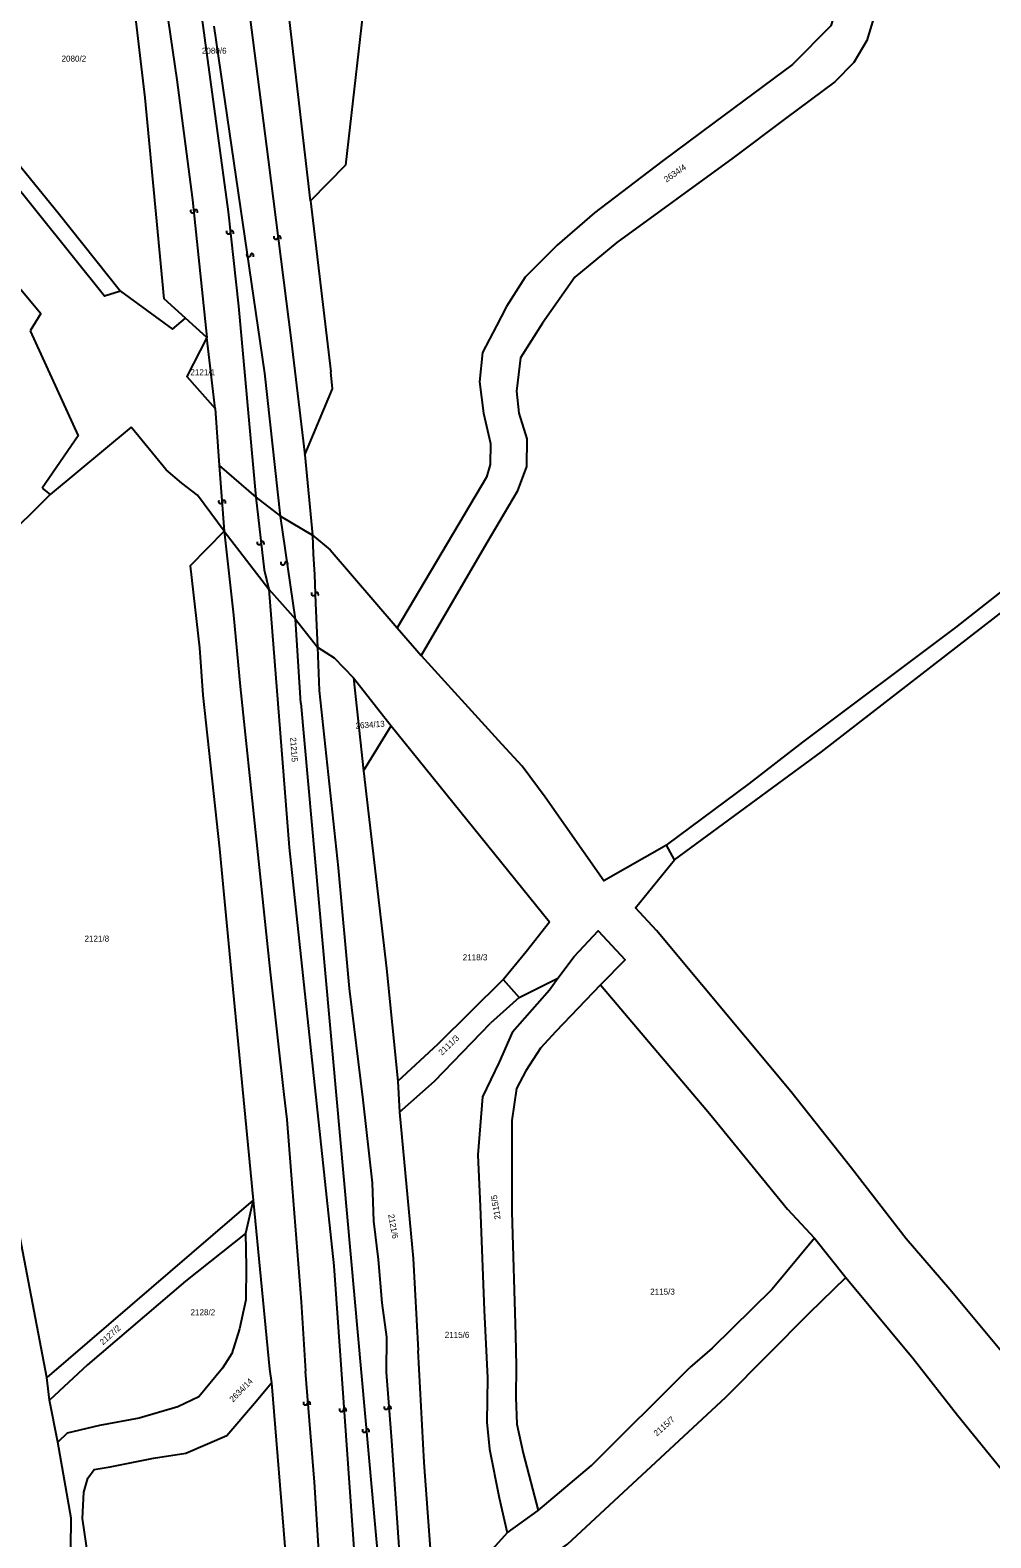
# Model space of a CAD drawing. Extents: x -581999 to -572728, y -1219553 to -1212032.
# Drawn here: x -576394 to -576076, y -1216348 to -1215848 of the extents above; entities that cross this region are included whole.
import ezdxf

# ---------------------------------------------------------------- set-up
doc = ezdxf.new("R2010")
doc.units = 0
for name, color, linetype in [('Vrstva 1', 7, 'Continuous'), ('Vrstva 2', 7, 'Continuous'), ('Vrstva 4', 7, 'Continuous'), ('Vrstva 6', 7, 'Continuous')]:
    doc.layers.add(name, color=color, linetype=linetype)

msp = doc.modelspace()

# ---------------------------------------------------------------- linework, layer by layer
at = {"layer": 'Vrstva 1'}
for p, q in [((-576356.273, -1215870.335), (-576360.8, -1215831.766)), ((-576450.435, -1215870.759), (-576390.81, -1215941.951)), ((-576349.894, -1215937.081), (-576356.273, -1215870.335)), ((-576342.862, -1215943.515), (-576349.894, -1215937.081)), ((-576390.81, -1215941.951), (-576394.345, -1215947.753)), ((-576394.345, -1215947.753), (-576378.44, -1215982.562)), ((-576335.832, -1215949.947), (-576342.862, -1215943.515)), ((-576333.009, -1215973.521), (-576331.724, -1215992.401)), ((-576378.44, -1215982.562), (-576390.368, -1215999.967)), ((-576331.724, -1215992.401), (-576319.52, -1216002.887)), ((-576390.368, -1215999.967), (-576387.717, -1216002.039)), ((-576319.52, -1216002.887), (-576311.344, -1216009.21)), ((-576311.344, -1216009.21), (-576300.762, -1216015.51)), ((-576232.162, -1216169.034), (-576219.332, -1216162.616)), ((-576234.385, -1216180.427), (-576222.069, -1216166.467)), ((-576236.168, -1216346.782), (-576225.819, -1216339.308))]:
    msp.add_line(p, q, dxfattribs=at)
for points in [[(-576104.129, -1215760.392), (-576107.967, -1215765.027), (-576112.258, -1215772.037), (-576115.046, -1215779.052), (-576115.435, -1215786.377), (-576115.542, -1215795.229), (-576116.26, -1215804.993), (-576118.784, -1215815.057), (-576128.771, -1215846.461), (-576141.538, -1215859.243), (-576167.599, -1215878.707), (-576184.873, -1215891.479)], [(-576099.875, -1215781.163), (-576102.579, -1215791.296), (-576102.749, -1215805.334), (-576107.105, -1215817.834), (-576113.38, -1215840.092), (-576116.819, -1215851.371), (-576121.111, -1215858.681), (-576127.493, -1215865.072), (-576143.855, -1215877.236), (-576161.128, -1215890.312), (-576199.747, -1215918.364), (-576213.7, -1215929.925), (-576224.392, -1215945.15), (-576231.735, -1215956.722), (-576233.062, -1215967.695), (-576232.245, -1215975.013), (-576229.639, -1215983.553), (-576229.744, -1215992.696)], [(-576301.376, -1215904.608), (-576308.701, -1215841.562)], [(-576284.007, -1215842.251), (-576289.823, -1215892.731), (-576301.376, -1215904.608)], [(-576407.912, -1215880.699), (-576385.122, -1215908.586), (-576364.389, -1215934.537)], [(-576184.873, -1215891.479), (-576207.144, -1215908.589), (-576219.586, -1215919.238), (-576230.225, -1215929.891), (-576236.347, -1215939.638), (-576239.725, -1215946.035), (-576244.334, -1215954.869), (-576245.346, -1215964.623), (-576243.962, -1215974.992), (-576241.673, -1215985.056), (-576241.753, -1215992.066), (-576243.004, -1215996.331), (-576272.67, -1216046.337)], [(-576301.376, -1215904.608), (-576294.599, -1215961.296)], [(-576131.913, -1216087.486), (-576070.48, -1216039.887), (-576023.639, -1216003.814), (-575990.874, -1215977.966), (-575937.957, -1215933.045), (-575902.923, -1215903.954)], [(-576364.389, -1215934.537), (-576347.226, -1215947.102), (-576342.862, -1215943.515)], [(-576335.832, -1215949.947), (-576342.461, -1215962.859), (-576333.009, -1215973.521)], [(-576333.009, -1215973.521), (-576335.832, -1215949.947)], [(-576303.244, -1215988.909), (-576294.052, -1215967.017), (-576294.599, -1215961.296)], [(-576360.859, -1215979.732), (-576387.717, -1216002.039), (-576394.727, -1216009.041), (-576402.035, -1216016.029), (-576418.589, -1216026.667), (-576441.437, -1216019.645)], [(-576330.06, -1216014.211), (-576338.879, -1216002.306), (-576344.081, -1215998.229), (-576349.281, -1215993.838), (-576360.859, -1215979.732)], [(-576303.244, -1215988.909), (-576300.762, -1216015.51)], [(-576229.744, -1215992.696), (-576232.802, -1216000.997), (-576242.91, -1216018.045), (-576264.662, -1216055.487)], [(-576138.079, -1216084.214), (-576087.326, -1216046.159), (-576033.978, -1216004.263)], [(-576330.06, -1216014.211), (-576341.295, -1216025.771), (-576338.198, -1216052.991), (-576337.135, -1216068.632), (-576331.56, -1216119.697), (-576327.137, -1216166.261)], [(-576330.06, -1216014.211), (-576315.251, -1216033.451), (-576306.415, -1216043.396), (-576299.017, -1216052.734)], [(-576300.762, -1216015.51), (-576294.916, -1216020.401), (-576272.67, -1216046.337)], [(-576388.901, -1216295.197), (-576414.233, -1216163.069), (-576441.437, -1216019.645)], [(-576272.67, -1216046.337), (-576264.662, -1216055.487)], [(-576299.017, -1216052.734), (-576293.54, -1216056.279), (-576287.138, -1216062.854)], [(-576264.662, -1216055.487), (-576239.148, -1216083.623)], [(-576287.138, -1216062.854), (-576274.675, -1216078.815)], [(-576287.138, -1216062.854), (-576283.784, -1216093.808)], [(-576283.784, -1216093.808), (-576274.675, -1216078.815)], [(-576274.675, -1216078.815), (-576222.101, -1216143.864)], [(-576183.302, -1216118.434), (-576204.041, -1216130.302), (-576223.494, -1216102.534), (-576231.196, -1216092.263), (-576239.148, -1216083.623)], [(-576183.302, -1216118.434), (-576155.708, -1216097.949), (-576138.079, -1216084.214)], [(-576180.601, -1216123.332), (-576131.913, -1216087.486)], [(-576283.784, -1216093.808), (-576276.199, -1216159.432)], [(-576180.601, -1216123.332), (-576183.302, -1216118.434)], [(-576141.996, -1216200.242), (-576186.561, -1216146.758), (-576193.599, -1216139.293), (-576180.601, -1216123.332)], [(-576237.427, -1216163.075), (-576229.85, -1216153.787), (-576222.101, -1216143.864)], [(-576213.918, -1216155.426), (-576206.002, -1216146.923), (-576196.947, -1216156.57), (-576205.191, -1216164.823)], [(-576222.069, -1216166.467), (-576219.332, -1216162.616), (-576213.918, -1216155.426)], [(-576276.199, -1216159.432), (-576272.451, -1216196.781)], [(-576272.451, -1216196.781), (-576259.065, -1216184.4), (-576237.427, -1216163.075)], [(-576237.427, -1216163.075), (-576232.162, -1216169.034), (-576241.667, -1216177.529)], [(-576327.137, -1216166.261), (-576320.45, -1216236.33)], [(-576205.191, -1216164.823), (-576219.969, -1216180.298), (-576225.125, -1216185.801), (-576229.965, -1216193.368), (-576233.088, -1216199.216)], [(-576205.191, -1216164.823), (-576169.038, -1216207.514)], [(-576271.888, -1216207.106), (-576260.225, -1216196.789), (-576241.667, -1216177.529)], [(-576234.385, -1216180.427), (-576238.833, -1216190.536), (-576244.324, -1216201.961), (-576245.902, -1216221.229), (-576245.08, -1216238.43), (-576243.775, -1216272.822)], [(-576272.451, -1216196.781), (-576271.888, -1216207.106)], [(-576233.088, -1216199.216), (-576234.568, -1216209.882), (-576234.575, -1216240.155), (-576233.348, -1216281.077)], [(-576089.274, -1216265.949), (-576103.782, -1216249.15), (-576121.862, -1216225.633), (-576141.996, -1216200.242)], [(-576271.888, -1216207.106), (-576267.342, -1216255.619), (-576265.651, -1216286.227)], [(-576169.038, -1216207.514), (-576143.187, -1216239.323), (-576134.145, -1216248.953)], [(-576320.45, -1216236.33), (-576388.901, -1216295.197)], [(-576320.45, -1216236.33), (-576322.95, -1216247.34)], [(-576320.45, -1216236.33), (-576314.955, -1216292.406)], [(-576322.95, -1216247.34), (-576342.829, -1216263.16), (-576375.412, -1216291.017)], [(-576322.95, -1216247.34), (-576322.731, -1216258.35), (-576322.852, -1216269.358), (-576324.997, -1216278.99), (-576327.465, -1216287.244), (-576330.575, -1216292.058)], [(-576134.145, -1216248.953), (-576148.25, -1216265.791), (-576168.152, -1216285.376), (-576175.575, -1216291.892)], [(-576134.145, -1216248.953), (-576123.792, -1216262.019)], [(-576163.651, -1216301.688), (-576135.798, -1216273.7), (-576123.792, -1216262.019)], [(-576123.792, -1216262.019), (-576101.405, -1216288.828), (-576086.725, -1216307.724), (-576064.031, -1216335.539)], [(-576039.198, -1216326.221), (-576062.144, -1216298.52), (-576089.274, -1216265.949)], [(-576243.775, -1216272.822), (-576242.703, -1216295.23), (-576242.872, -1216310.012), (-576241.956, -1216318.948), (-576238.748, -1216335.1), (-576236.168, -1216346.782)], [(-576233.348, -1216281.077), (-576233.157, -1216291.451), (-576233.276, -1216301.763)], [(-576260.488, -1216367.055), (-576263.726, -1216323.415), (-576265.651, -1216286.227)], [(-576375.412, -1216291.017), (-576387.991, -1216302.639)], [(-576330.575, -1216292.058), (-576338.414, -1216301.57), (-576345.438, -1216304.899), (-576358.222, -1216308.642), (-576371.405, -1216311.138), (-576382.122, -1216313.634), (-576385.177, -1216316.667)], [(-576314.955, -1216292.406), (-576314.356, -1216296.937)], [(-576225.819, -1216339.308), (-576208.177, -1216324.362), (-576175.575, -1216291.892)], [(-576387.991, -1216302.639), (-576388.901, -1216295.197)], [(-576381.263, -1216382.312), (-576375.804, -1216376.039), (-576374.896, -1216368.137), (-576375.164, -1216354.826), (-576377.081, -1216341.93), (-576376.576, -1216333.192), (-576375.294, -1216328.615), (-576373.206, -1216325.703), (-576367.853, -1216324.87), (-576353.434, -1216321.959), (-576342.729, -1216320.295), (-576329.103, -1216314.471), (-576319.943, -1216303.654), (-576314.356, -1216296.937)], [(-576314.356, -1216296.937), (-576309.57, -1216355.38)], [(-576385.177, -1216316.667), (-576387.991, -1216302.639)], [(-576233.276, -1216301.763), (-576232.953, -1216310.614), (-576230.858, -1216320.237), (-576225.819, -1216339.308)], [(-576223.978, -1216356.143), (-576216.111, -1216350.473), (-576163.651, -1216301.688)], [(-576381.263, -1216382.312), (-576380.829, -1216341.895), (-576385.177, -1216316.667)], [(-576236.168, -1216346.782), (-576243.04, -1216354.341), (-576252.302, -1216363.275), (-576260.488, -1216367.055)]]:
    msp.add_lwpolyline(points, dxfattribs=at)
at = {"layer": 'Vrstva 4'}
for p, q in [((-576343.303, -1215800.847), (-576328.697, -1215908.152)), ((-576316.577, -1215961.759), (-576333.365, -1215846.555)), ((-576328.697, -1215908.152), (-576325.293, -1215939.507)), ((-576325.293, -1215939.507), (-576319.52, -1216002.887)), ((-576311.344, -1216009.21), (-576316.577, -1215961.759)), ((-576331.724, -1215992.401), (-576330.06, -1216014.211)), ((-576319.52, -1216002.887), (-576316.776, -1216027)), ((-576306.415, -1216043.396), (-576311.344, -1216009.21)), ((-576304.612, -1216071.274), (-576306.415, -1216043.396)), ((-576304.612, -1216071.274), (-576277.388, -1216373.788)), ((-576308.5, -1216119.224), (-576293.655, -1216258.15)), ((-576293.655, -1216258.15), (-576285.38, -1216374.742))]:
    msp.add_line(p, q, dxfattribs=at)
for points in [[(-576351.456, -1215824.892), (-576345.707, -1215864.405), (-576340.581, -1215904.21), (-576335.832, -1215949.947)], [(-576322.532, -1215835.573), (-576315.423, -1215890.795), (-576307.754, -1215950.94)], [(-576364.389, -1215934.537), (-576369.762, -1215936.197), (-576413.691, -1215881.523)], [(-576307.754, -1215950.94), (-576303.244, -1215988.909)], [(-576330.06, -1216014.211), (-576326.971, -1216042.06), (-576324.764, -1216065.833)], [(-576300.762, -1216015.51), (-576300.464, -1216021.87)], [(-576300.464, -1216021.87), (-576300.117, -1216028.622)], [(-576316.776, -1216027), (-576315.251, -1216033.451), (-576308.5, -1216119.224)], [(-576300.117, -1216028.622), (-576299.695, -1216038.271)], [(-576299.695, -1216038.271), (-576299.017, -1216052.734)], [(-576299.017, -1216052.734), (-576298.56, -1216067.119)], [(-576324.764, -1216065.833), (-576319.484, -1216115.334), (-576314.743, -1216160.648)], [(-576298.56, -1216067.119), (-576292.16, -1216125.988), (-576288.6, -1216165.98)], [(-576314.743, -1216160.648), (-576310.209, -1216201.231), (-576309.281, -1216209.492), (-576307.495, -1216232.207), (-576304.518, -1216270.052), (-576303.076, -1216293.096)], [(-576288.6, -1216165.98), (-576284.069, -1216202.968), (-576280.982, -1216230.499), (-576280.446, -1216243.23), (-576278.891, -1216255.958), (-576277.695, -1216270.405), (-576276.126, -1216281.754), (-576276.257, -1216293.445)], [(-576297.152, -1216375.827), (-576300.12, -1216329.945), (-576303.076, -1216293.096)], [(-576276.257, -1216293.445), (-576274.507, -1216316.195), (-576272.171, -1216349.878), (-576270.733, -1216372.897)]]:
    msp.add_lwpolyline(points, dxfattribs=at)
at = {"layer": 'Vrstva 6'}
for points in [[(-576338.898, -1215908.517), (-576338.803, -1215907.666), (-576339.533, -1215907.454), (-576339.85, -1215907.708), (-576339.895, -1215908.124), (-576340.046, -1215908.431), (-576340.295, -1215908.598), (-576340.522, -1215908.642), (-576340.785, -1215908.586), (-576341.04, -1215908.322), (-576341.08, -1215907.712), (-576341.01, -1215907.543)], [(-576326.984, -1215915.512), (-576326.889, -1215914.661), (-576327.619, -1215914.449), (-576327.936, -1215914.703), (-576327.981, -1215915.119), (-576328.132, -1215915.426), (-576328.381, -1215915.593), (-576328.608, -1215915.637), (-576328.871, -1215915.581), (-576329.126, -1215915.317), (-576329.166, -1215914.707), (-576329.096, -1215914.538)], [(-576311.293, -1215917.26), (-576311.198, -1215916.409), (-576311.928, -1215916.197), (-576312.245, -1215916.451), (-576312.29, -1215916.867), (-576312.441, -1215917.174), (-576312.69, -1215917.341), (-576312.917, -1215917.385), (-576313.18, -1215917.329), (-576313.435, -1215917.065), (-576313.475, -1215916.455), (-576313.405, -1215916.286)], [(-576320.301, -1215923.089), (-576320.206, -1215922.238), (-576320.936, -1215922.026), (-576321.253, -1215922.28), (-576321.298, -1215922.696), (-576321.449, -1215923.003), (-576321.698, -1215923.17), (-576321.925, -1215923.214), (-576322.188, -1215923.158), (-576322.443, -1215922.894), (-576322.483, -1215922.284), (-576322.413, -1215922.115)], [(-576329.599, -1216004.986), (-576329.504, -1216004.135), (-576330.234, -1216003.923), (-576330.551, -1216004.177), (-576330.596, -1216004.593), (-576330.747, -1216004.9), (-576330.996, -1216005.067), (-576331.223, -1216005.111), (-576331.486, -1216005.055), (-576331.741, -1216004.791), (-576331.781, -1216004.181), (-576331.711, -1216004.012)], [(-576316.814, -1216018.684), (-576316.719, -1216017.833), (-576317.449, -1216017.621), (-576317.766, -1216017.875), (-576317.811, -1216018.291), (-576317.962, -1216018.598), (-576318.211, -1216018.765), (-576318.438, -1216018.809), (-576318.701, -1216018.753), (-576318.956, -1216018.489), (-576318.996, -1216017.879), (-576318.926, -1216017.71)], [(-576308.969, -1216025.388), (-576308.874, -1216024.537), (-576309.604, -1216024.325), (-576309.921, -1216024.579), (-576309.966, -1216024.995), (-576310.117, -1216025.302), (-576310.366, -1216025.469), (-576310.593, -1216025.513), (-576310.856, -1216025.457), (-576311.111, -1216025.193), (-576311.151, -1216024.583), (-576311.081, -1216024.414)], [(-576298.799, -1216035.588), (-576298.704, -1216034.737), (-576299.434, -1216034.525), (-576299.751, -1216034.779), (-576299.796, -1216035.195), (-576299.947, -1216035.502), (-576300.196, -1216035.669), (-576300.423, -1216035.713), (-576300.686, -1216035.657), (-576300.941, -1216035.393), (-576300.981, -1216034.783), (-576300.911, -1216034.614)], [(-576301.464, -1216304.264), (-576301.369, -1216303.413), (-576302.099, -1216303.201), (-576302.416, -1216303.455), (-576302.461, -1216303.871), (-576302.612, -1216304.178), (-576302.861, -1216304.345), (-576303.088, -1216304.389), (-576303.351, -1216304.333), (-576303.606, -1216304.069), (-576303.646, -1216303.459), (-576303.576, -1216303.29)], [(-576289.52, -1216306.442), (-576289.425, -1216305.591), (-576290.155, -1216305.379), (-576290.472, -1216305.633), (-576290.517, -1216306.049), (-576290.668, -1216306.356), (-576290.917, -1216306.523), (-576291.144, -1216306.567), (-576291.407, -1216306.511), (-576291.662, -1216306.247), (-576291.702, -1216305.637), (-576291.632, -1216305.468)], [(-576274.679, -1216305.716), (-576274.584, -1216304.865), (-576275.314, -1216304.653), (-576275.631, -1216304.907), (-576275.676, -1216305.323), (-576275.827, -1216305.63), (-576276.076, -1216305.797), (-576276.303, -1216305.841), (-576276.566, -1216305.785), (-576276.821, -1216305.521), (-576276.861, -1216304.911), (-576276.791, -1216304.742)], [(-576281.919, -1216313.336), (-576281.824, -1216312.485), (-576282.554, -1216312.273), (-576282.871, -1216312.527), (-576282.916, -1216312.943), (-576283.067, -1216313.25), (-576283.316, -1216313.417), (-576283.543, -1216313.461), (-576283.806, -1216313.405), (-576284.061, -1216313.141), (-576284.101, -1216312.531), (-576284.031, -1216312.362)]]:
    msp.add_open_spline(points, degree=2, dxfattribs=at)

# ---------------------------------------------------------------- texts
at = {"layer": 'Vrstva 2'}
for s, p in [('2080/2', (-576383.975, -1215858.337)), ('2080/6', (-576337.419, -1215855.727)), ('2121/1', (-576341.243, -1215962.449)), ('2121/8', (-576376.361, -1216150.478)), ('2118/3', (-576250.883, -1216156.677)), ('2115/3', (-576188.69, -1216267.664)), ('2128/2', (-576341.186, -1216274.505)), ('2115/6', (-576256.853, -1216282.009))]:
    msp.add_text(s, height=2, dxfattribs=at).set_placement(p)
for s, rotation, p in [('2634/4', 34.49075, (-576183.285, -1215898.509)), ('2634/13', 4.16157, (-576286.373, -1216079.804)), ('2121/5', 273.42151, (-576308.116, -1216082.727)), ('2111/3', 43.38368, (-576257.809, -1216188.353)), ('2115/5', 98.9364, (-576238.312, -1216242.54)), ('2121/6', 280.0482, (-576275.634, -1216241.154)), ('2127/2', 42.12028, (-576370.228, -1216284.519)), ('2634/14', 45.76284, (-576327.073, -1216303.505)), ('2115/7', 41.58807, (-576186.496, -1216314.807))]:
    msp.add_text(s, height=2, rotation=rotation, dxfattribs=at).set_placement(p)

doc.saveas('drawing.dxf')
